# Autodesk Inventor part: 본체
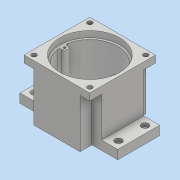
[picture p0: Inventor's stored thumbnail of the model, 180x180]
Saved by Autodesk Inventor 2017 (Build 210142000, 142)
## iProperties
Part Number: 본체
Material: 일반
Document SubType Name: Modeling
Designer: user
Density: 1 g/cm^3
Appearance: 기본값
Author: user
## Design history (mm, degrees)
sketch "스케치1"
  geometry: L1 (-33, 47)-(33, 47); L2 (33, 47)-(33, -47); L3 (33, -47)-(-33, -47); L4 (-33, -47)-(-33, 47); L5 (-33, 47)-(33, -47); L6 (33, 47)-(-33, -47); L7 (-70, -30)-(70, -30); L8 (70, -30)-(70, 30); L9 (70, 30)-(-70, 30); L10 (-70, 30)-(-70, -30); L11 (-70, -30)-(70, 30); L12 (70, -30)-(-70, 30); 3 further points
  constraints: 24 end point, 5 midpoint, 4 parallel, 2 horizontal, 2 perpendicular, 1 coincident
  dimensions: "d8" = 66 distance of L1.start L1.end; "d9" = 94 distance of L1.end L2.end; "d10" = 140 distance of L8.end L9.end; "d11" = 60 distance of L7.end L8.end
extrude "돌출1" new body sketch "스케치1" distance "d2" = 13; taper "d3" = 0 deg
sketch "스케치3"
  geometry: L1 (-33, 30)-(-33, 47) reference; L2 (33, -47)-(-33, -47); L3 (-33, -47)-(-33, 47); L4 (-33, 47)-(33, 47); L5 (33, 47)-(33, -47); L6 (33, -47)-(-33, 47); L7 (-33, -47)-(33, 47); L8 (-47, -30)-(47, -30); L9 (47, -30)-(47, 30); L10 (47, 30)-(-47, 30); L11 (-47, 30)-(-47, -30); L12 (-47, -30)-(47, 30); L13 (47, -30)-(-47, 30); L14 (-33, 30)-(-70, 30) reference; 1 further point
  constraints: 24 end point, 4 midpoint, 4 parallel, 2 horizontal, 2 perpendicular, 1 collinear
  dimensions: "d12" = 94 distance between parallel lines of L9 L11
extrude "돌출2" join sketch "스케치3" distance "d13" = 57; taper "d14" = 0 deg
sketch "스케치4"
  geometry: L1 (-47, -47)-(47, -47); L2 (47, -47)-(47, 47); L3 (47, 47)-(-47, 47); L4 (-47, 47)-(-47, -47); L5 (-47, -47)-(47, 47); L6 (47, -47)-(-47, 47); 1 further point
  constraints: 12 end point, 2 midpoint, 2 parallel, 1 horizontal, 1 perpendicular
  dimensions: "d15" = 94 distance of L2.end L3.end; "d16" = 94 distance of L1.end L2.end
extrude "돌출3" join sketch "스케치4" distance "d17" = 10; taper "d18" = 0 deg
sketch "스케치5"
  geometry: L1 (-40, 40)-(40, 40); L2 (40, 40)-(40, -40); L3 (40, -40)-(-40, -40); L4 (-40, -40)-(-40, 40); L5 (-40, 40)-(40, -40); L6 (40, 40)-(-40, -40); C1 r 3.5 at (40, 40); C2 r 3.5 at (-40, 40); C3 r 3.5 at (-40, -40); C4 r 3.5 at (40, -40); 1 further point
  constraints: 12 end point, 4 centre point, 4 coincident, 2 midpoint, 2 parallel, 1 horizontal, 1 perpendicular
  dimensions: "d19" = 80 distance of L1.start L1.end; "d20" = 80 distance of L1.end L2.end; "d21" = 7 diameter of C1; "d22" = 7 diameter of C2; "d23" = 7 diameter of C3; "d24" = 7 diameter of C4
extrude "돌출4" cut sketch "스케치5" distance "d25" = 10; taper "d26" = 0 deg
sketch "스케치6"
  geometry: C1 r 43 at (0, 0); 1 further point
  constraints: 1 centre point, 1 coincident
  dimensions: "d27" = 86 diameter of C1
extrude "돌출5" cut sketch "스케치6" distance "d28" = 9; taper "d29" = 0 deg
sketch "스케치7"
  geometry: C1 r 40 at (0, 0); 1 further point
  constraints: 1 centre point, 1 coincident
  dimensions: "d30" = 80 diameter of C1
extrude "돌출6" cut sketch "스케치7" distance "d31" = 62; taper "d32" = 0 deg
sketch "스케치8"
  geometry: C1 r 21 at (0, 11); C2 r 15 at (0, -20); 1 further point
  constraints: 2 centre point, 2 vertical alignment
  dimensions: "d33" = 42 diameter of C1; "d34" = 30 diameter of C2; "d35" = 11 distance of point (0, 0) C1.centre; "d36" = 20 distance of C2.centre point (0, 0)
extrude "돌출7" join sketch "스케치8" distance "d37" = 7; taper "d38" = 0 deg
sketch "스케치9"
  geometry: C1 r 17.5 at (0, 11); 1 further point
  constraints: 1 centre point, 1 vertical alignment
  dimensions: "d39" = 35 diameter of C1; "d40" = 11 distance of point (0, 0) C1.centre
extrude "돌출8" cut sketch "스케치9" distance "d41" = 10; taper "d42" = 0 deg
sketch "스케치10"
  geometry: C1 r 12.5 at (0, 0); 1 further point
  constraints: 1 centre point, 1 vertical alignment
  dimensions: "d43" = 25 diameter of C1; "d44" = 11 distance of C1.centre point (0, -11)
extrude "돌출9" cut sketch "스케치10" distance "d45" = 4.7; taper "d46" = 0 deg
sketch "스케치11"
  geometry: C1 r 16 at (0, 0); 1 further point
  constraints: 1 centre point, 1 vertical alignment
  dimensions: "d47" = 11 distance of point (0, -11) C1.centre; "d48" = 32 diameter of C1
extrude "돌출10" cut sketch "스케치11" distance "d49" = 8.3; taper "d50" = 0 deg
sketch "스케치12"
  geometry: C1 r 11 at (0, -20); 1 further point
  constraints: 1 centre point, 1 vertical alignment
  dimensions: "d51" = 20 distance of C1.centre point (0, 0); "d52" = 22 diameter of C1
extrude "돌출11" cut sketch "스케치12" distance "d53" = 7; taper "d54" = 0 deg
sketch "스케치13"
  geometry: C1 r 9.5 at (0, 0); 1 further point
  constraints: 1 centre point, 1 vertical alignment
  dimensions: "d55" = 19 diameter of C1
extrude "돌출12" cut sketch "스케치13" distance "d56" = 3; taper "d57" = 0 deg
sketch "스케치14"
  geometry: C1 r 12.5 at (0, 11) reference; C2 r 27.5 at (0, 11); 1 further point
  constraints: 1 centre point, 1 coincident
  dimensions: "d58" = 55 diameter of C2
extrude "돌출13" join sketch "스케치14" distance "d59" = 7; taper "d60" = 0 deg
sketch "스케치15"
  geometry: C1 r 5 at (60, 19); C2 r 5 at (60, -19); 3 further points
  constraints: 2 centre point, 2 coincident
  dimensions: "d61" = 60 horizontal distance of point (60, 19) point (0, 0); "d62" = 19 vertical distance of point (0, 0) point (60, 19); "d63" = 19 vertical distance of point (60, -19) point (0, 0); "d64" = 60 horizontal distance of point (60, -19) point (0, 0); "d65" = 10 diameter of C1; "d66" = 10 diameter of C2
extrude "돌출14" cut sketch "스케치15" distance "d67" = 5; taper "d68" = 0 deg
sketch "스케치17"
  geometry: C1 r 5 at (60, 19) reference; C2 r 5 at (60, -19) reference; C3 r 2.25 at (60, 19); C4 r 2.25 at (60, -19); 1 further point
  constraints: 2 centre point, 2 coincident
  dimensions: "d69" = 4.5 diameter of C3; "d70" = 4.5 diameter of C4
extrude "돌출15" cut sketch "스케치17" distance "d71" = 50; taper "d72" = 0 deg
sketch "스케치18"
  geometry: A1 r 4 centre (-36, 0) between (-36.19, -3.995) and (-36.19, 3.995); A2 r 3 centre (-36.333, -6.992) between (-36.19, -3.995) and (-39.279, -7.559); A3 r 3 centre (-36.333, 6.992) between (-39.279, 7.559) and (-36.19, 3.995); A4 r 40 centre (0, 0) between (-39.279, 7.559) and (-39.279, -7.559) reference; 1 further point
  constraints: 8 point on circle, 4 tangent, 3 centre point, 1 horizontal alignment
  dimensions: "d73" = 8 diameter of A1; "d74" = 36 distance of point (0, 0) A1.centre; "d75" = 6 diameter of A2; "d76" = 6 diameter of A3
extrude "돌출16" join sketch "스케치18" stored distance "d77" = 0; taper "d78" = 0 deg
sketch "스케치19"
  geometry: C1 r 43 at (0, 0) reference; A1 r 3 centre (-36.333, 6.992) between (-39.279, 7.559) and (-36.19, 3.995) reference; A2 r 40 centre (0, 0) between (39.279, 7.559) and (-39.279, 7.559) reference; A3 r 3 centre (36.333, 6.992) between (36.19, 3.995) and (39.279, 7.559) reference; A4 r 4 centre (36, 0) between (36.19, 3.995) and (36.19, -3.995) reference; A5 r 3 centre (36.333, -6.992) between (39.279, -7.559) and (36.19, -3.995) reference; A6 r 40 centre (0, 0) between (-39.279, -7.559) and (39.279, -7.559) reference; A7 r 3 centre (-36.333, -6.992) between (-36.19, -3.995) and (-39.279, -7.559) reference; A8 r 4 centre (-36, 0) between (-36.19, -3.995) and (-36.19, 3.995) reference; 3 further points
  constraints: 2 coincident
hole "구멍1" sketch "스케치19" at (36, 0), (-36, 0) diameter "d79" = 3.242; stored, may be unused: countersink angle "d83" = 90 deg, drill point angle "d85" = 118 deg; dims "d80" = 7, "d81" = 4, "d82" = 2, "d84" = 9
sketch "스케치20" dims "d8" = 66, "d9" = 94, "d10" = 140, "d11" = 60
  geometry: L1 (80, -80)-(-14, -80) reference; L2 (0, 0)-(66, 0) reference; 3 further points
  constraints: 1 midpoint, 1 vertical alignment, 1 other
  dimensions: "d86" = 40 distance from line of point (33, -40) L1
feature "엠보싱1" sketch "스케치20" dims "d8" = 66, "d9" = 94, "d10" = 140, "d11" = 60, "d12" = 94, "d87" = 0.5, "d88" = 0
node "솔리드1"
mirror "미러1"
mirror "미러2"
node "투영된 루프1"
